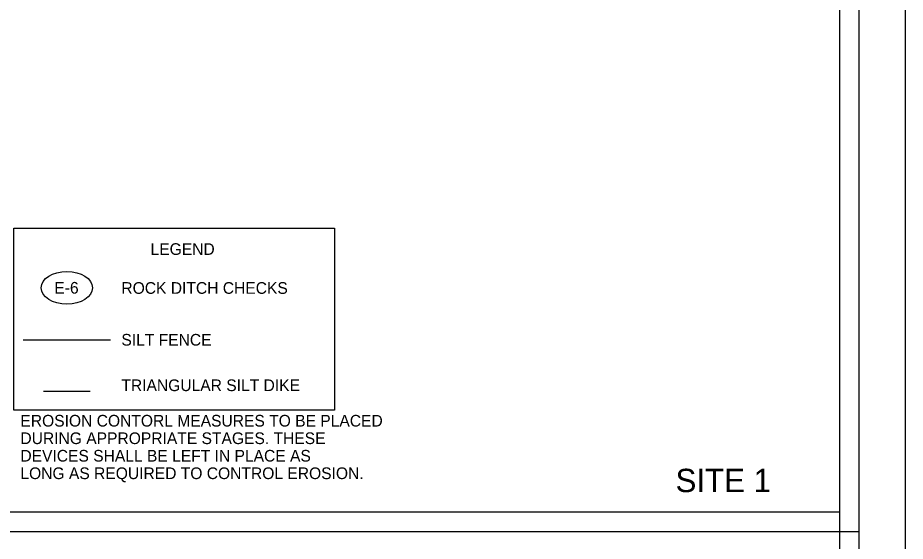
# Model space of a CAD drawing. Extents: x 814841 to 962585, y -174183 to 1802800.
# Drawn here: x 820260 to 820716.4, y 1802262 to 1802531 of the extents above; entities that cross this region are included whole.
import ezdxf

# ---------------------------------------------------------------- set-up
doc = ezdxf.new("R2010")
doc.units = 0
for name, color, linetype in [('_Silt Dike Legend', 7, 'Continuous'), ('Default', 7, 'Continuous'), ('Legend', 7, 'Continuous'), ('R_Border', 7, 'Continuous'), ('R_Border Plan-Plan', 7, 'Continuous'), ('R_No Plot', 7, 'Continuous')]:
    doc.layers.add(name, color=color, linetype=linetype)

# ---------------------------------------------------------------- blocks, each defined once
blk = doc.blocks.new('E-6')
at = {"layer": 'Default'}
blk.add_ellipse((0, 0), major_axis=(13.15, 0), ratio=0.638788, dxfattribs=at)
blk.add_text('E-6', height=6, dxfattribs=at).set_placement((-6.43, -3))

msp = doc.modelspace()

# ---------------------------------------------------------------- linework, layer by layer
at = {"layer": '_Silt Dike Legend'}
msp.add_line((820273.18, 1802339.12), (820297.18, 1802339.12), dxfattribs=at)
at = {"layer": 'Legend'}
msp.add_line((820262.75, 1802365.5), (820307.77, 1802365.5), dxfattribs=at)
msp.add_lwpolyline([(820257.98, 1802422.91), (820422.98, 1802422.91), (820422.98, 1802329.38), (820257.98, 1802329.38)], close=True, dxfattribs=at)
at = {"layer": 'R_Border'}
msp.add_line((820692.68, 1801753.3), (820692.68, 1802780.6), dxfattribs=at)
at = {"layer": 'R_Border Plan-Plan'}
msp.add_line((819111.78, 1802266.95), (820692.68, 1802266.95), dxfattribs=at)
at = {"layer": 'R_No Plot'}
for points in [[(819049.74, 1802800.08), (820716.44, 1802800.08), (820716.44, 1801733.39), (819049.74, 1801733.39)], [(820682.68, 1802276.95), (819121.78, 1802276.95), (819121.78, 1802770.6), (820369.48, 1802770.6), (820369.48, 1802721.2), (820457.18, 1802721.2), (820577.68, 1802721.2), (820577.68, 1802609.54), (820682.68, 1802609.54)], [(820682.68, 1802276.95), (819121.78, 1802276.95), (819121.78, 1802770.6), (820369.48, 1802770.6), (820369.48, 1802721.2), (820457.18, 1802721.2), (820577.68, 1802721.2), (820577.68, 1802609.54), (820682.68, 1802609.54)], [(820682.68, 1802276.95), (819121.78, 1802276.95), (819121.78, 1802770.6), (820369.48, 1802770.6), (820369.48, 1802721.2), (820457.18, 1802721.2), (820577.68, 1802721.2), (820577.68, 1802609.54), (820682.68, 1802609.54)], [(820682.68, 1802276.95), (819121.78, 1802276.95), (819121.78, 1802770.6), (820369.48, 1802770.6), (820369.48, 1802721.2), (820457.18, 1802721.2), (820577.68, 1802721.2), (820577.68, 1802609.54), (820682.68, 1802609.54)], [(820682.68, 1802276.95), (819121.78, 1802276.95), (819121.78, 1802770.6), (820369.48, 1802770.6), (820369.48, 1802721.2), (820457.18, 1802721.2), (820577.68, 1802721.2), (820577.68, 1802609.54), (820682.68, 1802609.54)], [(820682.68, 1802276.95), (819121.78, 1802276.95), (819121.78, 1802770.6), (820369.48, 1802770.6), (820369.48, 1802721.2), (820457.18, 1802721.2), (820577.68, 1802721.2), (820577.68, 1802609.54), (820682.68, 1802609.54)], [(819121.78, 1802770.6), (820369.48, 1802770.6), (820369.48, 1802721.2), (820457.18, 1802721.2), (820577.68, 1802721.2), (820577.68, 1802609.54), (820682.68, 1802609.54), (820682.68, 1801763.3), (819121.78, 1801763.3)], [(820682.68, 1802276.95), (819121.78, 1802276.95), (819121.78, 1802770.6), (820369.48, 1802770.6), (820369.48, 1802721.2), (820457.18, 1802721.2), (820577.68, 1802721.2), (820577.68, 1802609.54), (820682.68, 1802609.54)]]:
    msp.add_lwpolyline(points, close=True, dxfattribs=at)

# ---------------------------------------------------------------- block references
at = {"layer": 'Legend', "rotation": -1.8065126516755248e-10}
msp.add_blockref('E-6', (820285.26, 1802392.22), dxfattribs=at)

# ---------------------------------------------------------------- texts
at = {"layer": 'Legend'}
for s, p in [('LEGEND', (820328.3, 1802409.12)), ('ROCK DITCH CHECKS', (820313.3, 1802389.12)), ('SILT FENCE', (820313.3, 1802362.5)), ('TRIANGULAR SILT DIKE', (820313.3, 1802339.12)), ('EROSION CONTORL MEASURES TO BE PLACED', (820261.36, 1802320.89)), ('DURING APPROPRIATE STAGES. THESE ', (820261.36, 1802311.89)), ('DEVICES SHALL BE LEFT IN PLACE AS ', (820261.36, 1802302.89)), ('LONG AS REQUIRED TO CONTROL EROSION.', (820261.36, 1802293.89))]:
    msp.add_text(s, height=6, dxfattribs=at).set_placement(p)
at = {"layer": 'R_Border'}
msp.add_text('SITE 1', height=12, dxfattribs=at).set_placement((820598.32, 1802287.19))

doc.saveas('drawing.dxf')
